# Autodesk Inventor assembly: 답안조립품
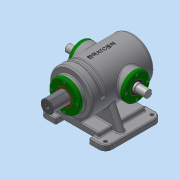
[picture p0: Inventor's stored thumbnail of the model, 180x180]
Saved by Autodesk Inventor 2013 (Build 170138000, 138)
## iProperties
Created: 2018-06
Part Number: 답안조립품
Document SubType Name: Assembly
Designer: Administrator
Author: Administrator
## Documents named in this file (13)
- C:\Users\Administrator\Desktop\380628V1008\답안조립품.iam
- C:\Users\Administrator\Desktop\380628V1008\본체.ipt
- C:\Users\Administrator\Desktop\380628V1008\가변스프링.ipt
- C:\Users\Administrator\Desktop\380628V1008\베어링 6205.ipt
- 베어링 6205.ipt
- C:\Users\Administrator\Desktop\380628V1008\볼트 M4.ipt
- C:\Users\Administrator\Desktop\380628V1008\부시.ipt
- C:\Users\Administrator\Desktop\380628V1008\슬라이드 커버.ipt
- C:\Users\Administrator\Desktop\380628V1008\슬라이드.ipt
- C:\Users\Administrator\Desktop\380628V1008\오일실.ipt
- 오일실.ipt
- C:\Users\Administrator\Desktop\380628V1008\축 커버.ipt
- C:\Users\Administrator\Desktop\380628V1008\편심축.ipt
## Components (1 placed, 1 different names)
1. 가변스프링:1
